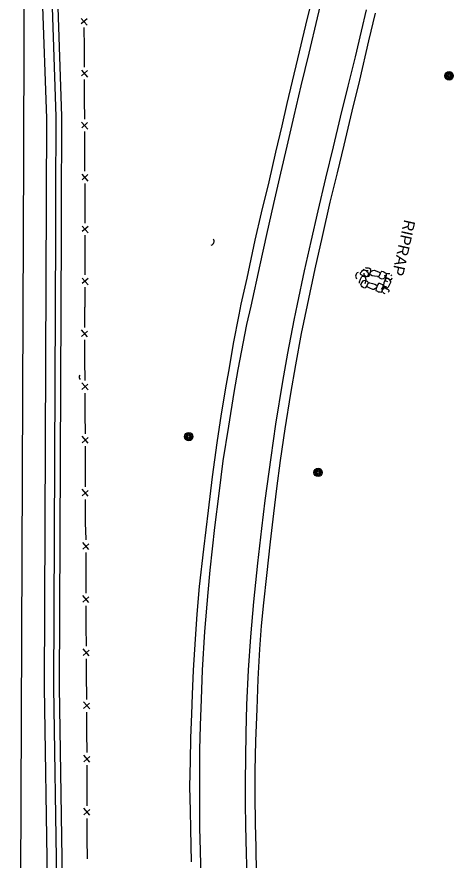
# Model space of a CAD drawing. Extents: x 588843 to 2552415, y 180129 to 269402.
# Drawn here: x 594080.5 to 594311.3, y 187487.4 to 187932.2 of the extents above; entities that cross this region are included whole.
import ezdxf

# ---------------------------------------------------------------- set-up
doc = ezdxf.new("R2010")
doc.units = 0
for name, color, linetype in [('Default', 7, 'Continuous'), ('E_DRN', 7, 'Continuous'), ('E_DRN_RipRap', 7, 'Continuous'), ('E_DRN_RipRap_Text', 7, 'Continuous'), ('E_FEN_P', 7, 'Continuous'), ('E_MISCPROP', 7, 'Continuous'), ('E_RDWY', 7, 'Continuous'), ('E_RDWY_Gravel', 7, 'Continuous'), ('P_RDWY_PavtEdge', 7, 'Continuous'), ('P_RDWY_ShldAgg', 7, 'Continuous'), ('P_RDWY_ShldPaved', 7, 'Continuous')]:
    doc.layers.add(name, color=color, linetype=linetype)

# ---------------------------------------------------------------- blocks, each defined once
blk = doc.blocks.new('CULV2')
at = {"layer": 'E_DRN'}
blk.add_arc((19.7, 14.8), 24.6, 216.8699, 323.1301, dxfattribs=at)
blk = doc.blocks.new('POLE')
at = {"layer": 'Default'}
for radius in [4.46, 3.35, 2.23, 1.12]:
    blk.add_circle((0, 0), radius, dxfattribs=at)
blk = doc.blocks.new('RIPRT')
at = {"layer": 'E_DRN_RipRap_Text'}
blk.add_text('RIPRAP', height=12, dxfattribs=at).set_placement((-0.14, -3.59))

msp = doc.modelspace()

# ---------------------------------------------------------------- linework, layer by layer
at = {"layer": 'E_DRN_RipRap'}
for p, q in [((594265.1, 187799.69), (594264.45, 187799.78)), ((594266.08, 187799.6), (594265.1, 187799.69)), ((594266.59, 187799.38), (594266.08, 187799.6)), ((594267.42, 187798.95), (594266.59, 187799.38)), ((594261.91, 187793.87), (594262.43, 187794.95)), ((594261.93, 187796.39), (594261.96, 187797.09)), ((594262.25, 187796.17), (594261.93, 187796.39)), ((594261.96, 187797.09), (594262.19, 187797.51)), ((594262.19, 187797.51), (594262.52, 187797.94)), ((594262.97, 187795.72), (594262.25, 187796.17)), ((594262.43, 187794.95), (594262.66, 187795.29)), ((594262.52, 187797.94), (594262.99, 187798.35)), ((594262.66, 187795.29), (594263.49, 187795.47)), ((594264.4, 187795), (594262.97, 187795.72)), ((594262.99, 187798.35), (594263.38, 187798.59)), ((594263.14, 187799.09), (594264.3, 187798.58)), ((594263.38, 187798.59), (594263.54, 187798.68)), ((594264.18, 187795.11), (594263.49, 187795.47)), ((594263.54, 187798.68), (594264.1, 187798.64)), ((594263.71, 187797.07), (594263.6, 187796.45)), ((594263.6, 187796.45), (594263.73, 187795.99)), ((594263.73, 187795.99), (594263.83, 187795.88)), ((594263.83, 187795.88), (594264.7, 187795.49)), ((594264.1, 187798.64), (594264.69, 187798.31)), ((594264.56, 187794.63), (594264.18, 187795.11)), ((594264.3, 187798.58), (594264.98, 187798.48)), ((594264.88, 187794.89), (594264.4, 187795)), ((594264.69, 187798.31), (594265.21, 187797.92)), ((594264.7, 187795.49), (594265.43, 187795.27)), ((594265.19, 187795.02), (594264.88, 187794.89)), ((594264.98, 187798.48), (594265.84, 187798.32)), ((594265.54, 187795.42), (594265.19, 187795.02)), ((594265.21, 187797.92), (594265.77, 187797.5)), ((594265.43, 187795.27), (594266.12, 187795.33)), ((594265.84, 187796.09), (594265.54, 187795.42)), ((594265.77, 187797.5), (594265.94, 187797.15)), ((594266.01, 187796.62), (594265.84, 187796.09)), ((594265.94, 187797.15), (594266.01, 187796.62)), ((594266.12, 187795.33), (594266.57, 187795.78)), ((594266.57, 187795.78), (594266.64, 187796.15)), ((594266.64, 187796.15), (594266.91, 187797.1)), ((594266.91, 187797.1), (594267.26, 187798.01)), ((594266.93, 187796.66), (594267.2, 187797.49)), ((594267.19, 187796.11), (594266.93, 187796.66)), ((594268.04, 187795.64), (594267.19, 187796.11)), ((594267.2, 187797.49), (594267.61, 187798.03)), ((594267.26, 187798.01), (594267.42, 187798.95)), ((594267.61, 187798.03), (594268.46, 187798.48)), ((594269.34, 187795.33), (594268.04, 187795.64)), ((594268.46, 187798.48), (594269.09, 187798.51)), ((594269.09, 187798.51), (594270.57, 187797.96)), ((594270.81, 187795.16), (594269.34, 187795.33)), ((594270.57, 187797.96), (594271.66, 187797.46)), ((594270.81, 187795.16), (594271.36, 187795.31)), ((594271.36, 187795.31), (594271.84, 187795.7)), ((594271.63, 187795), (594271.73, 187795.49)), ((594271.77, 187794.69), (594271.63, 187795)), ((594271.66, 187797.46), (594272, 187797.23)), ((594271.73, 187795.49), (594272.44, 187796.93)), ((594272.17, 187794.34), (594271.77, 187794.69)), ((594271.84, 187795.7), (594272.19, 187796.4)), ((594272, 187797.23), (594272.19, 187796.4)), ((594272.44, 187796.93), (594272.87, 187797.65)), ((594272.87, 187797.65), (594273.09, 187797.97)), ((594273.09, 187797.97), (594273.79, 187797.95)), ((594273.79, 187797.95), (594274.22, 187797.73)), ((594274.22, 187797.73), (594274.65, 187797.4)), ((594274.67, 187794.72), (594274.25, 187794.15)), ((594274.62, 187795.9), (594274.64, 187795.21)), ((594274.64, 187795.21), (594275.07, 187794.73)), ((594274.65, 187797.4), (594275.07, 187796.94)), ((594275.05, 187795.24), (594274.67, 187794.72)), ((594275.37, 187795.83), (594275.05, 187795.24)), ((594275.07, 187796.94), (594275.32, 187796.55)), ((594275.07, 187794.73), (594275.42, 187794.64)), ((594275.22, 187794.95), (594275.08, 187794.09)), ((594275.32, 187795.63), (594275.22, 187794.95)), ((594275.81, 187796.8), (594275.32, 187795.63)), ((594275.32, 187796.55), (594275.41, 187796.39)), ((594275.41, 187796.39), (594275.37, 187795.83)), ((594276.47, 187796.71), (594275.81, 187796.8)), ((594277.44, 187796.62), (594276.47, 187796.71)), ((594278.35, 187795.58), (594278.08, 187796.06)), ((594261.34, 187792.4), (594261.91, 187793.87)), ((594261.35, 187791.77), (594261.34, 187792.4)), ((594262.11, 187790.83), (594262.18, 187791.39)), ((594262.2, 187790.67), (594262.11, 187790.83)), ((594262.18, 187791.39), (594262.52, 187791.97)), ((594262.43, 187790.27), (594262.2, 187790.67)), ((594262.83, 187789.79), (594262.43, 187790.27)), ((594262.52, 187791.97), (594262.92, 187792.47)), ((594262.92, 187792.47), (594263.37, 187793.02)), ((594263.37, 187793.02), (594263.72, 187793.18)), ((594263.72, 187793.18), (594264.26, 187793.24)), ((594264.52, 187792.6), (594264.19, 187791.31)), ((594264.26, 187793.24), (594264.78, 187793.05)), ((594264.71, 187794.07), (594264.52, 187792.6)), ((594264.71, 187794.07), (594264.56, 187794.63)), ((594264.78, 187793.05), (594265.44, 187792.73)), ((594265.82, 187791.57), (594265.06, 187790.17)), ((594265.71, 187791.36), (594265.33, 187790.68)), ((594265.48, 187789.84), (594265.33, 187790.68)), ((594265.44, 187792.73), (594265.82, 187792.37)), ((594266.2, 187791.73), (594265.71, 187791.36)), ((594265.82, 187792.37), (594265.95, 187792.06)), ((594265.95, 187792.06), (594265.82, 187791.57)), ((594266.76, 187791.85), (594266.2, 187791.73)), ((594266.76, 187791.85), (594268.22, 187791.62)), ((594268.22, 187791.62), (594269.51, 187791.25)), ((594269.51, 187791.25), (594270.33, 187790.74)), ((594270.33, 187790.74), (594270.57, 187790.18)), ((594270.89, 187790.68), (594270.57, 187789.74)), ((594270.97, 187791.04), (594270.89, 187790.68)), ((594271.44, 187791.47), (594270.97, 187791.04)), ((594272.13, 187791.5), (594271.44, 187791.47)), ((594272.85, 187791.25), (594272.13, 187791.5)), ((594272.85, 187794.06), (594272.17, 187794.34)), ((594273.37, 187793.89), (594272.85, 187794.06)), ((594273.7, 187790.82), (594272.85, 187791.25)), ((594273.91, 187793.97), (594273.37, 187793.89)), ((594273.8, 187790.71), (594273.7, 187790.82)), ((594273.9, 187790.23), (594273.8, 187790.71)), ((594274.25, 187794.15), (594273.91, 187793.97)), ((594274.18, 187790.54), (594274.44, 187792)), ((594274.18, 187790.54), (594274.3, 187789.98)), ((594274.44, 187792), (594274.83, 187793.27)), ((594274.46, 187793.68), (594274.9, 187793.06)), ((594274.83, 187793.27), (594275.35, 187794.09)), ((594275.08, 187794.09), (594274.97, 187793.48)), ((594274.97, 187793.48), (594275.09, 187793.01)), ((594275.09, 187793.01), (594275.2, 187792.9)), ((594275.2, 187792.9), (594276.07, 187792.51)), ((594275.35, 187794.09), (594275.92, 187794.32)), ((594275.42, 187794.64), (594276.36, 187794.31)), ((594275.92, 187794.32), (594276.73, 187794)), ((594276.36, 187794.31), (594277.25, 187793.91)), ((594276.98, 187790.6), (594276.41, 187789.55)), ((594276.73, 187794), (594277.24, 187793.55)), ((594277.63, 187792.04), (594276.98, 187790.6)), ((594277.24, 187793.55), (594277.64, 187792.67)), ((594277.25, 187793.91), (594278.17, 187793.68)), ((594277.64, 187792.67), (594277.63, 187792.04)), ((594278.17, 187793.68), (594278.65, 187794.49)), ((594263.24, 187789.44), (594262.83, 187789.79)), ((594263.66, 187789.2), (594263.24, 187789.44)), ((594264.36, 187789.15), (594263.66, 187789.2)), ((594264.59, 187789.46), (594264.36, 187789.15)), ((594265.06, 187790.17), (594264.59, 187789.46)), ((594265.81, 187789.6), (594265.48, 187789.84)), ((594266.87, 187789.05), (594265.81, 187789.6)), ((594268.33, 187788.43), (594266.87, 187789.05)), ((594268.95, 187788.43), (594268.33, 187788.43)), ((594269.83, 187788.85), (594268.95, 187788.43)), ((594270.26, 187789.37), (594269.83, 187788.85)), ((594270.18, 187788.84), (594269.98, 187787.92)), ((594269.98, 187787.92), (594270.79, 187787.45)), ((594270.57, 187789.74), (594270.18, 187788.84)), ((594270.57, 187790.18), (594270.26, 187789.37)), ((594270.79, 187787.45), (594271.29, 187787.21)), ((594271.29, 187787.21), (594272.26, 187787.07)), ((594272.26, 187787.07), (594272.91, 187786.95)), ((594272.91, 187786.95), (594273.46, 187788.1)), ((594272.95, 187788.57), (594273.28, 187789.23)), ((594273.28, 187789.23), (594273.65, 187789.61)), ((594273.33, 187787.34), (594273.4, 187787.9)), ((594273.42, 187787.18), (594273.33, 187787.34)), ((594273.4, 187787.9), (594273.74, 187788.47)), ((594273.65, 187786.78), (594273.42, 187787.18)), ((594273.46, 187788.1), (594273.58, 187788.77)), ((594273.58, 187788.77), (594273.77, 187789.62)), ((594273.65, 187789.61), (594273.96, 187789.73)), ((594273.74, 187788.47), (594274.14, 187788.98)), ((594273.77, 187789.62), (594273.9, 187790.23)), ((594274.34, 187786.33), (594273.85, 187786.72)), ((594273.96, 187789.73), (594274.44, 187789.6)), ((594274.14, 187788.98), (594274.59, 187789.53)), ((594274.19, 187789.61), (594274.51, 187789.84)), ((594274.3, 187789.98), (594274.65, 187789.48)), ((594274.81, 187786.08), (594274.34, 187786.33)), ((594274.44, 187789.6), (594275.84, 187788.8)), ((594274.51, 187789.84), (594275.02, 187790.01)), ((594274.65, 187789.48), (594275.32, 187789.08)), ((594275.02, 187790.01), (594275.57, 187789.93)), ((594276.17, 187789.22), (594275.32, 187789.08)), ((594275.84, 187788.8), (594276.53, 187788.32)), ((594276.41, 187789.55), (594276.17, 187789.22)), ((594276.53, 187788.32), (594276.84, 187788.08)), ((594276.78, 187787.39), (594276.53, 187786.98)), ((594276.84, 187788.08), (594276.78, 187787.39))]:
    msp.add_line(p, q, dxfattribs=at)
at = {"layer": 'E_FEN_P'}
for p, q in [((594114.47, 187931.35), (594117.64, 187927.71)), ((594117.64, 187931.18), (594114.54, 187928.44)), ((594114.59, 187903.96), (594117.78, 187900.33)), ((594117.76, 187903.81), (594114.67, 187901.05)), ((594114.72, 187876.57), (594117.92, 187872.95)), ((594117.9, 187876.42), (594114.81, 187873.67)), ((594114.85, 187849.19), (594118.04, 187845.56)), ((594118.02, 187849.03), (594114.93, 187846.28)), ((594114.95, 187821.81), (594118.12, 187818.17)), ((594118.12, 187821.64), (594115.02, 187818.9)), ((594114.96, 187794.42), (594118.14, 187790.78)), ((594118.14, 187794.26), (594115.03, 187791.52)), ((594114.66, 187763.59), (594117.84, 187766.39)), ((594117.9, 187763.42), (594114.67, 187767.15)), ((594118.08, 187735.4), (594114.81, 187739.11)), ((594114.83, 187735.55), (594117.99, 187738.37)), ((594118.2, 187707.36), (594114.94, 187711.08)), ((594114.95, 187707.52), (594118.12, 187710.34)), ((594118.25, 187679.32), (594115, 187683.05)), ((594115, 187679.49), (594118.18, 187682.3)), ((594118.58, 187651.29), (594115.33, 187655.02)), ((594115.33, 187651.47), (594118.51, 187654.27)), ((594118.58, 187623.26), (594115.33, 187626.99)), ((594115.33, 187623.43), (594118.51, 187626.24)), ((594118.76, 187595.24), (594115.48, 187598.94)), ((594115.51, 187595.38), (594118.66, 187598.22)), ((594118.97, 187567.2), (594115.71, 187570.92)), ((594115.73, 187567.36), (594118.9, 187570.18)), ((594119.08, 187539.17), (594115.82, 187542.88)), ((594115.83, 187539.33), (594119, 187542.14)), ((594119.08, 187511.13), (594115.83, 187514.86)), ((594115.84, 187511.3), (594119.01, 187514.11))]:
    msp.add_line(p, q, dxfattribs=at)
for points in [[(594115.94, 187926.49), (594115.99, 187916.03)], [(594115.99, 187916.03), (594116.04, 187905.57)], [(594116.08, 187899.1), (594116.13, 187888.64)], [(594116.13, 187888.64), (594116.18, 187878.19)], [(594116.21, 187871.72), (594116.26, 187862.51), (594116.27, 187861.26)], [(594116.27, 187861.26), (594116.31, 187850.8)], [(594116.34, 187844.33), (594116.38, 187833.87)], [(594116.38, 187833.87), (594116.41, 187825.27), (594116.42, 187823.42)], [(594116.42, 187816.94), (594116.42, 187806.49)], [(594116.42, 187806.49), (594116.43, 187796.03)], [(594116.43, 187789.56), (594116.44, 187779.1)], [(594116.42, 187768.4), (594116.44, 187779.1)], [(594116.49, 187751.07), (594116.43, 187761.77)], [(594116.55, 187740.37), (594116.49, 187751.07)], [(594116.63, 187723.04), (594116.58, 187733.74)], [(594116.68, 187712.33), (594116.63, 187723.04)], [(594116.75, 187695), (594116.74, 187698.16), (594116.71, 187705.71)], [(594116.75, 187684.3), (594116.75, 187695)], [(594116.76, 187666.97), (594116.75, 187677.67)], [(594117.08, 187656.27), (594117.08, 187656.9), (594116.76, 187665.12), (594116.76, 187666.97)], [(594117.08, 187638.94), (594117.08, 187649.65)], [(594117.08, 187628.24), (594117.08, 187638.94)], [(594117.11, 187610.91), (594117.08, 187614.51), (594117.08, 187621.61)], [(594117.21, 187600.21), (594117.11, 187610.91)], [(594117.37, 187582.88), (594117.27, 187593.58)], [(594117.46, 187572.18), (594117.45, 187574.94), (594117.37, 187582.88)], [(594117.52, 187554.85), (594117.48, 187565.55)], [(594117.56, 187544.14), (594117.52, 187554.85)], [(594117.58, 187526.81), (594117.58, 187537.52)], [(594117.58, 187516.11), (594117.58, 187526.81)], [(594117.61, 187498.78), (594117.58, 187500.42), (594117.58, 187509.48)], [(594117.8, 187488.08), (594117.61, 187498.78)]]:
    msp.add_lwpolyline(points, dxfattribs=at)
at = {"layer": 'E_RDWY'}
for points in [[(594204.12, 187779.52), (594208.85, 187801.44), (594212.44, 187817.45), (594216.12, 187833.75), (594219.89, 187849.7), (594223.26, 187863.88), (594226.91, 187879.94), (594230.58, 187895.72), (594234.73, 187912.94), (594239.27, 187931.72), (594243.32, 187948.86)], [(594228.57, 187780.63), (594232.33, 187798.24), (594235.82, 187813.68), (594239.52, 187829.79), (594243.61, 187847.13), (594247.57, 187863.55), (594251.39, 187879.2), (594255.33, 187895.54), (594259.23, 187911.13), (594262.33, 187924.57), (594265.09, 187935.9)], [(594177.81, 187477.31), (594177.4, 187492.57), (594177.16, 187504.32), (594177.04, 187518.97), (594177.04, 187531.26), (594177.1, 187545.57), (594177.39, 187558.49), (594177.9, 187572.35), (594178.57, 187587.68), (594179.75, 187608.05), (594181.48, 187628.59), (594182.47, 187640.42), (594184.97, 187662.89), (594187.22, 187680.86), (594189.43, 187698.03), (594192.32, 187716.22), (594195.23, 187734.1), (594197.39, 187746.27), (594201.98, 187769.84), (594204.12, 187779.52)], [(594202.17, 187473.9), (594201.71, 187490.68), (594201.42, 187505.64), (594201.28, 187517.31), (594201.16, 187528.75), (594201.3, 187541.49), (594201.56, 187554.44), (594201.96, 187569.36), (594202.7, 187587.58), (594203.94, 187605.15), (594205.53, 187623.67), (594207.64, 187644.12), (594209.74, 187662.27), (594211.6, 187677.09), (594214.67, 187699.74), (594217.25, 187717.44), (594220.9, 187739.9), (594223.61, 187754.73), (594226.9, 187772.14), (594228.57, 187780.63)]]:
    msp.add_lwpolyline(points, dxfattribs=at)
at = {"layer": 'E_RDWY_Gravel'}
for points in [[(594198.98, 187780.6), (594201.99, 187794.32), (594206.34, 187814.37), (594209.66, 187828.73), (594213.65, 187845.12), (594217.26, 187860.85), (594220.48, 187874.65), (594223.16, 187886.54), (594228.75, 187909.95), (594233.11, 187927.78), (594237.26, 187945.12)], [(594233.94, 187780.16), (594237.95, 187799.28), (594241.84, 187816.34), (594245.91, 187834.4), (594249.71, 187849.82), (594253.29, 187864.57), (594257.55, 187882.4), (594261.56, 187898.79), (594266.33, 187919.58), (594269.83, 187934.17)], [(594172.68, 187486.6), (594172.32, 187503.71), (594172.13, 187513.56), (594171.9, 187526.01), (594172.13, 187539.77), (594172.33, 187551.93), (594172.8, 187564.44), (594173.17, 187574.84), (594173.77, 187587.55), (594174.73, 187603.9), (594175.7, 187617.14), (594176.99, 187631.71), (594179.14, 187651.35), (594181.63, 187671.82), (594183.77, 187689.59), (594186.23, 187707.55), (594188.56, 187722.87), (594191.15, 187738.37), (594192.68, 187747.01), (594194.89, 187759.9), (594197.86, 187775.09), (594198.98, 187780.6)], [(594207.02, 187480.33), (594206.74, 187494.26), (594206.45, 187506.57), (594206.34, 187521.53), (594206.38, 187534.58), (594206.62, 187550.27), (594207.28, 187567.11), (594207.83, 187582.95), (594208.7, 187598.73), (594209.65, 187610.93), (594210.83, 187623.14), (594212.37, 187637.53), (594214.41, 187655.34), (594216.17, 187670.16), (594217.81, 187683.5), (594219.59, 187698.21), (594222.12, 187714.87), (594225.13, 187733.51), (594227.76, 187748.58), (594230.81, 187765.12), (594233.94, 187780.16)]]:
    msp.add_lwpolyline(points, dxfattribs=at)
at = {"layer": 'P_RDWY_PavtEdge'}
for p, q in [((594096.29, 187878.74), (594086.37, 188174.07)), ((594095.08, 187578.66), (594096.29, 187878.74)), ((594080.53, 186947.13), (594084.04, 187818.33)), ((594099.87, 187278.64), (594095.08, 187578.66))]:
    msp.add_line(p, q, dxfattribs=at)
msp.add_arc((536719.48, 188049.55), 57365.03, 359.769059, 0.1893986, dxfattribs=at)
at = {"layer": 'P_RDWY_ShldAgg'}
for p, q in [((594104.26, 187879.74), (594098.51, 188051.01)), ((594103.08, 187578.63), (594104.04, 187818.25)), ((594107.87, 187278.77), (594103.08, 187578.79))]:
    msp.add_line(p, q, dxfattribs=at)
msp.add_arc((536719.48, 188049.55), 57385.03, 359.769059, 359.8304528, dxfattribs=at)
at = {"layer": 'P_RDWY_ShldPaved'}
for p, q in [((594101.26, 187879.69), (594096.5, 188021.37)), ((594100.08, 187578.69), (594101.04, 187818.26)), ((594104.87, 187278.72), (594100.08, 187578.69))]:
    msp.add_line(p, q, dxfattribs=at)
msp.add_arc((536719.48, 188049.55), 57382.03, 359.769059, 359.8303981, dxfattribs=at)

# ---------------------------------------------------------------- block references
at = {"layer": 'E_DRN'}
for p, xscale, yscale, rotation in [((594183.11, 187811.75), 0.08693672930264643, 0.08693672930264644, 70.34988949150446), ((594260.58, 187797.37), 0.08593846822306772, 0.08593846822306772, -103.04527501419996), ((594113.85, 187743.12), 0.055796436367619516, 0.055796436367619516, -85.4245464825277)]:
    msp.add_blockref('CULV2', p, dxfattribs=dict(at, xscale=xscale, yscale=yscale, rotation=rotation))
at = {"layer": 'E_DRN_RipRap_Text', "xscale": 0.5000000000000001, "yscale": 0.5, "rotation": -102.57777672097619}
msp.add_blockref('RIPRT', (594286.73, 187825.05), dxfattribs=at)
at = {"layer": 'E_MISCPROP', "xscale": 0.5000000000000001}
for p, yscale, rotation in [((594308.63, 187901.08), 0.5, -102.57777672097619), ((594171.23, 187710.77), 0.5000000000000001, -90.51737743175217), ((594239.47, 187691.93), 0.5000000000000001, -90.51737743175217)]:
    msp.add_blockref('POLE', p, dxfattribs=dict(at, yscale=yscale, rotation=rotation))

doc.saveas('drawing.dxf')
